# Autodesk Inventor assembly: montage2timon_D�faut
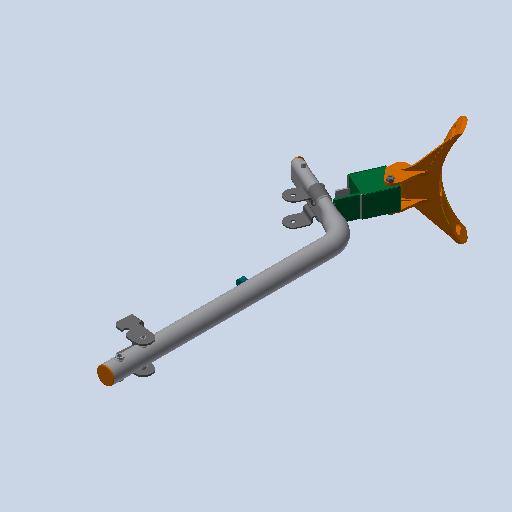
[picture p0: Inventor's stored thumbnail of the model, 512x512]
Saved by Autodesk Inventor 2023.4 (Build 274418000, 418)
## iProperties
Created: 2011-01
Part Number: montage2timon_D�faut
Document SubType Name: Assembly
Designer: eric
Mass: 224.141 g
Surface Area: 2423.19 cm^2
Volume: 224.141 cm^3
Density: 1 g/cm^3
Author: eric
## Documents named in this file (17)
- C:\Users\bruno\Documents\1-Cours-2024-25\TSsI\7-Dynamique\chariot de golf\chariot_de_golf\chariot_de_golf_trolem\montage2timon_Defaut.iam
- C:\Users\bruno\Documents\1-Cours-2024-25\TSsI\7-Dynamique\chariot de golf\chariot_de_golf\chariot_de_golf_trolem\31verrou_bas_Defaut.ipt
- C:\Users\bruno\Documents\1-Cours-2024-25\TSsI\7-Dynamique\chariot de golf\chariot_de_golf\chariot_de_golf_trolem\58embout_ovale_Defaut.ipt
- C:\Users\bruno\Documents\1-Cours-2024-25\TSsI\7-Dynamique\chariot de golf\chariot_de_golf\chariot_de_golf_trolem\bead60_Defaut.ipt
- C:\Users\bruno\Documents\1-Cours-2024-25\TSsI\7-Dynamique\chariot de golf\chariot_de_golf\chariot_de_golf_trolem\35Vis_CBLZ_M6_55.ipt
- C:\Users\bruno\Documents\1-Cours-2024-25\TSsI\7-Dynamique\chariot de golf\chariot_de_golf\chariot_de_golf_trolem\bead50_Defaut.ipt
- C:\Users\bruno\Documents\1-Cours-2024-25\TSsI\7-Dynamique\chariot de golf\chariot_de_golf\chariot_de_golf_trolem\bead51_Defaut.ipt
- C:\Users\bruno\Documents\1-Cours-2024-25\TSsI\7-Dynamique\chariot de golf\chariot_de_golf\chariot_de_golf_trolem\bead61_Defaut.ipt
- C:\Users\bruno\Documents\1-Cours-2024-25\TSsI\7-Dynamique\chariot de golf\chariot_de_golf\chariot_de_golf_trolem\bead52_Defaut.ipt
- C:\Users\bruno\Documents\1-Cours-2024-25\TSsI\7-Dynamique\chariot de golf\chariot_de_golf\chariot_de_golf_trolem\34support_avant_Defaut.ipt
- C:\Users\bruno\Documents\1-Cours-2024-25\TSsI\7-Dynamique\chariot de golf\chariot_de_golf\chariot_de_golf_trolem\2chappe_Defaut.ipt
- C:\Users\bruno\Documents\1-Cours-2024-25\TSsI\7-Dynamique\chariot de golf\chariot_de_golf\chariot_de_golf_trolem\2timon_Defaut.iam
- C:\Users\bruno\Documents\1-Cours-2024-25\TSsI\7-Dynamique\chariot de golf\chariot_de_golf\chariot_de_golf_trolem\bead53_Defaut.ipt
- C:\Users\bruno\Documents\1-Cours-2024-25\TSsI\7-Dynamique\chariot de golf\chariot_de_golf\chariot_de_golf_trolem\1carre_assemble_Defaut.iam
- C:\Users\bruno\Documents\1-Cours-2024-25\TSsI\7-Dynamique\chariot de golf\chariot_de_golf\chariot_de_golf_trolem\45bouchon_cylindrique_Defaut.ipt
- C:\Users\bruno\Documents\1-Cours-2024-25\TSsI\7-Dynamique\chariot de golf\chariot_de_golf\chariot_de_golf_trolem\53guide_cable_Defaut.ipt
- C:\Users\bruno\Documents\1-Cours-2024-25\TSsI\7-Dynamique\chariot de golf\chariot_de_golf\chariot_de_golf_trolem\36Ecrou H_ FR_ M6.ipt
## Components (16 placed, 16 different names)
1. 31verrou_bas_Defaut:1
2. 58embout_ovale_Defaut:1
3. bead60_Defaut:1
4. 35Vis_CBLZ_M6_55:1 — Logement:3
5. bead50_Defaut:1
6. bead51_Defaut:1
7. bead61_Defaut:1
8. bead52_Defaut:1
9. 34support_avant_Defaut:1 — Logement:1, Logement:2, Logement:3
10. 2chappe_Defaut:1
11. 2timon_Defaut:1 [sub-assembly]
12. bead53_Defaut:1
13. 1carre_assemble_Defaut:1 [sub-assembly] — Logement:1
14. 45bouchon_cylindrique_Defaut:1
15. 53guide_cable_Defaut:1
16. 36Ecrou H_ FR_ M6:1 — Logement:2
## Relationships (3: Insert 3)
- Logement:1 [Insert]: 34support_avant_Defaut:1 ↔ 1carre_assemble_Defaut:1
- Logement:2 [Insert]: 34support_avant_Defaut:1 ↔ 36Ecrou H_ FR_ M6:1
- Logement:3 [Insert]: 35Vis_CBLZ_M6_55:1 ↔ 34support_avant_Defaut:1
